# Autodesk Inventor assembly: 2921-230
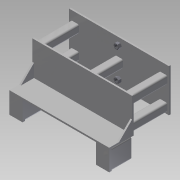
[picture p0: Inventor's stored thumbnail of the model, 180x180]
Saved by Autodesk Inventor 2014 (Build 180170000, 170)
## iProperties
Company: NHTSA/VRTC
Created: 2012-08
Part Number: 2921-230
Document SubType Name: Assembly
Designer: Mike Vanvoorhis
Mass: 11089.5 g
Surface Area: 5828.27 cm^2
Volume: 1410.88 cm^3
Density: 7.86 g/cm^3
Description: HONEYCOMB FRAME ASSEMBLY
Project: CHILD SIDE IMPACT SLED
Author: Dave Walker
Title: Honeycomb Frame Assembly
Subject: Child Side Impact Sled
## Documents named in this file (9)
- B:\VRTC_DWG\BIO\Non-P572\Child Side-Frontal Impact Sled\Side Impact Sled\Honeycomb_Fixture_Assembly.iam
- B:\VRTC_DWG\BIO\Non-P572\Child Side-Frontal Impact Sled\Side Impact Sled\Honeycomb_Fixture_Base.ipt
- B:\VRTC_DWG\BIO\Non-P572\Child Side-Frontal Impact Sled\Side Impact Sled\Honeycomb_Fixture_1_25_tube.ipt
- B:\VRTC_DWG\BIO\Non-P572\Child Side-Frontal Impact Sled\Side Impact Sled\Honeycomb_Fixture_Plate_2.ipt
- B:\VRTC_DWG\BIO\Non-P572\Child Side-Frontal Impact Sled\Side Impact Sled\Honeycomb_Fixture_Plate_1.ipt
- B:\VRTC_DWG\BIO\Non-P572\Child Side-Frontal Impact Sled\Side Impact Sled\Honeycomb_Fixture_2X3_tube.ipt
- B:\VRTC_DWG\BIO\Non-P572\Child Side-Frontal Impact Sled\Side Impact Sled\Honeycomb_Fixture_375_End_Cap.ipt
- B:\VRTC_DWG\BIO\Non-P572\Child Side-Frontal Impact Sled\Side Impact Sled\Honeycomb_Fixture_Gusset.ipt
- B:\VRTC_DWG\Inventor Support Files\Content Center\en-US\ANSI B18.2.2(09)\ANSI B18.2.2 - 1_2 - 13(2).ipt
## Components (16 placed, 8 different names)
1. Hexcell_Fixture_Base:1 — Mate:1, Flush:1, Flush:2, Flush:3, Flush:8, Flush:9, Flush:10, Flush:12, Flush:13, Flush:14, Flush:18, Insert:1, Insert:2
2. Honeycomb_Fixture_1_25_tube:1 — Flush:12, Flush:15, Flush:21
3. Honeycomb_Fixture_1_25_tube:2 — Flush:9, Flush:11, Flush:18
4. Honeycomb_Fixture_1_25_tube:3 — Flush:8, Flush:10, Flush:19
5. Honeycomb_Fixture_1_25_tube:4 — Flush:13, Flush:14, Flush:22
6. Honeycomb_Fixture_1_25_tube:5 — Flush:16, Flush:17, Flush:20
7. Honeycomb_Fixture_Plate_2:1 — Mate:1, Flush:1, Flush:2, Flush:3, Flush:4, Mate:2, Flush:11, Flush:15, Flush:16, Flush:17, Flush:19, Flush:20, Flush:21, Flush:22, Flush:23, Flush:25, Mate:12, Flush:26
8. Honeycomb_Fixture_Plate_1:1 — Flush:4, Mate:2, Mate:3, Mate:4, Mate:7, Flush:5, Flush:24, Mate:11, Mate:13, Flush:27, Flush:28
9. Honeycomb_Fixture_2X3_tube:1 — Mate:10, Flush:7, Flush:28
10. Honeycomb_Fixture_2X3_tube:2 — Mate:6, Flush:6, Flush:27
11. Honeycomb_Fixture_375_End_Cap:1 — Mate:7, Flush:5, Mate:10, Flush:7
12. Honeycomb_Fixture_375_End_Cap:2 — Mate:3, Mate:4, Mate:6, Flush:6
13. Honeycomb_Fixture_Gusset:1 — Flush:23, Flush:25, Mate:11
14. Honeycomb_Fixture_Gusset:2 — Flush:24, Mate:12, Flush:26, Mate:13
15. Hex Nut - Inch 1/2 - 13:1 — Insert:2
16. Hex Nut - Inch 1/2 - 13:2 — Insert:1
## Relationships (40: Flush 28, Mate 10, Insert 2)
- Mate:1: Hexcell_Fixture_Base:1 ↔ Honeycomb_Fixture_Plate_2:1
- Flush:1: Hexcell_Fixture_Base:1 ↔ Honeycomb_Fixture_Plate_2:1
- Flush:2: Hexcell_Fixture_Base:1 ↔ Honeycomb_Fixture_Plate_2:1
- Flush:3: Hexcell_Fixture_Base:1 ↔ Honeycomb_Fixture_Plate_2:1
- Flush:4: Honeycomb_Fixture_Plate_2:1 ↔ Honeycomb_Fixture_Plate_1:1
- Mate:2: Honeycomb_Fixture_Plate_2:1 ↔ Honeycomb_Fixture_Plate_1:1
- Mate:3: Honeycomb_Fixture_Plate_1:1 ↔ Honeycomb_Fixture_375_End_Cap:2
- Mate:4: Honeycomb_Fixture_Plate_1:1 ↔ Honeycomb_Fixture_375_End_Cap:2
- Mate:6: Honeycomb_Fixture_2X3_tube:2 ↔ Honeycomb_Fixture_375_End_Cap:2
- Mate:7: Honeycomb_Fixture_Plate_1:1 ↔ Honeycomb_Fixture_375_End_Cap:1
- Flush:5: Honeycomb_Fixture_Plate_1:1 ↔ Honeycomb_Fixture_375_End_Cap:1
- Mate:10: Honeycomb_Fixture_2X3_tube:1 ↔ Honeycomb_Fixture_375_End_Cap:1
- Flush:6: Honeycomb_Fixture_2X3_tube:2 ↔ Honeycomb_Fixture_375_End_Cap:2
- Flush:7: Honeycomb_Fixture_2X3_tube:1 ↔ Honeycomb_Fixture_375_End_Cap:1
- Flush:8: Hexcell_Fixture_Base:1 ↔ Honeycomb_Fixture_1_25_tube:3
- Flush:9: Hexcell_Fixture_Base:1 ↔ Honeycomb_Fixture_1_25_tube:2
- Flush:10: Hexcell_Fixture_Base:1 ↔ Honeycomb_Fixture_1_25_tube:3
- Flush:11: Honeycomb_Fixture_1_25_tube:2 ↔ Honeycomb_Fixture_Plate_2:1
- Flush:12: Hexcell_Fixture_Base:1 ↔ Honeycomb_Fixture_1_25_tube:1
- Flush:13: Hexcell_Fixture_Base:1 ↔ Honeycomb_Fixture_1_25_tube:4
- Flush:14: Hexcell_Fixture_Base:1 ↔ Honeycomb_Fixture_1_25_tube:4
- Flush:15: Honeycomb_Fixture_1_25_tube:1 ↔ Honeycomb_Fixture_Plate_2:1
- Flush:16: Honeycomb_Fixture_1_25_tube:5 ↔ Honeycomb_Fixture_Plate_2:1
- Flush:17: Honeycomb_Fixture_1_25_tube:5 ↔ Honeycomb_Fixture_Plate_2:1
- Flush:18: Hexcell_Fixture_Base:1 ↔ Honeycomb_Fixture_1_25_tube:2
- Flush:19: Honeycomb_Fixture_1_25_tube:3 ↔ Honeycomb_Fixture_Plate_2:1
- Flush:20: Honeycomb_Fixture_1_25_tube:5 ↔ Honeycomb_Fixture_Plate_2:1
- Flush:21: Honeycomb_Fixture_1_25_tube:1 ↔ Honeycomb_Fixture_Plate_2:1
- Flush:22: Honeycomb_Fixture_1_25_tube:4 ↔ Honeycomb_Fixture_Plate_2:1
- Flush:23: Honeycomb_Fixture_Plate_2:1 ↔ Honeycomb_Fixture_Gusset:1
- Flush:24: Honeycomb_Fixture_Plate_1:1 ↔ Honeycomb_Fixture_Gusset:2
- Flush:25: Honeycomb_Fixture_Plate_2:1 ↔ Honeycomb_Fixture_Gusset:1
- Mate:11: Honeycomb_Fixture_Plate_1:1 ↔ Honeycomb_Fixture_Gusset:1
- Mate:12: Honeycomb_Fixture_Plate_2:1 ↔ Honeycomb_Fixture_Gusset:2
- Flush:26: Honeycomb_Fixture_Plate_2:1 ↔ Honeycomb_Fixture_Gusset:2
- Mate:13: Honeycomb_Fixture_Plate_1:1 ↔ Honeycomb_Fixture_Gusset:2
- Flush:27: Honeycomb_Fixture_Plate_1:1 ↔ Honeycomb_Fixture_2X3_tube:2
- Flush:28: Honeycomb_Fixture_Plate_1:1 ↔ Honeycomb_Fixture_2X3_tube:1
- Insert:1: Hexcell_Fixture_Base:1 ↔ Hex Nut - Inch 1/2 - 13:2
- Insert:2: Hexcell_Fixture_Base:1 ↔ Hex Nut - Inch 1/2 - 13:1
